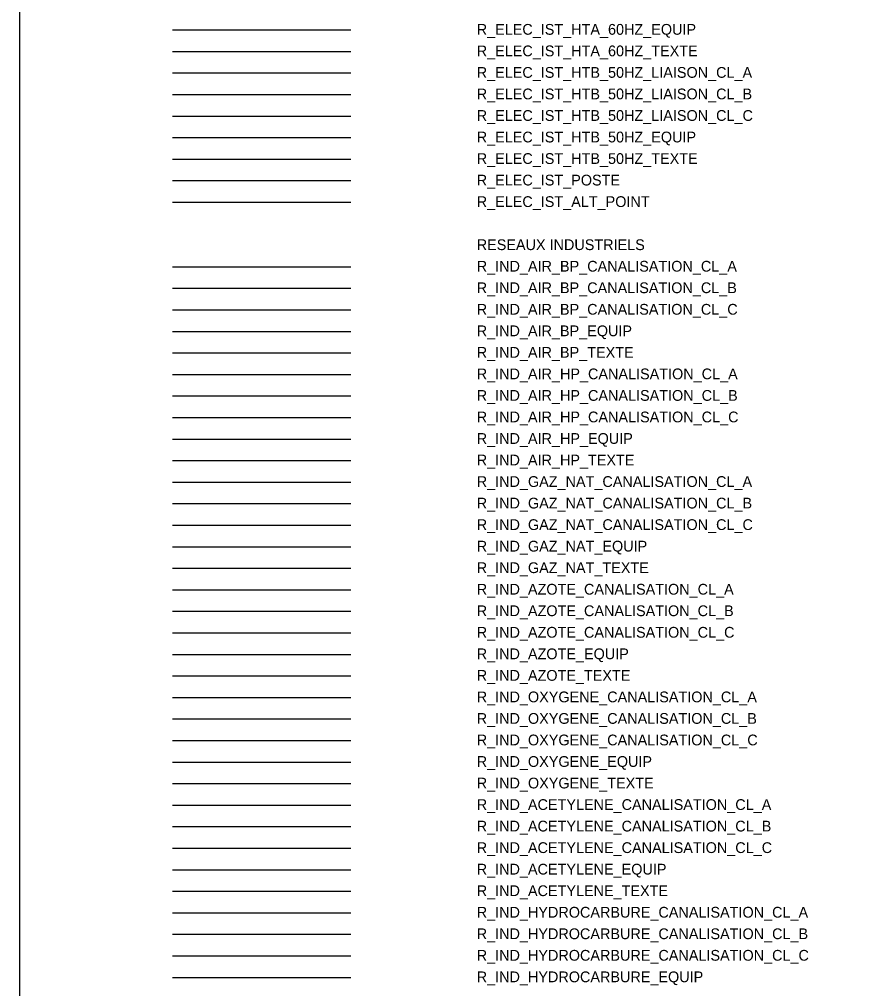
# Model space of a CAD drawing. Extents: x -60 to 214, y -380 to -21.
# Drawn here: x 33.07 to 72.77, y -155.95 to -110.94 of the extents above; entities that cross this region are included whole.
import ezdxf

# ---------------------------------------------------------------- set-up
doc = ezdxf.new("R2010")
doc.units = 0
for name, color, linetype in [('Default', 7, 'Continuous'), ('DH_TEXTE', 7, 'Continuous'), ('R_ELEC_IST_ALT_POINT', 7, 'Continuous'), ('R_ELEC_IST_HTA_60HZ_EQUIP', 7, 'Continuous'), ('R_ELEC_IST_HTA_60HZ_TEXTE', 7, 'Continuous'), ('R_ELEC_IST_HTB_50HZ_EQUIP', 7, 'Continuous'), ('R_ELEC_IST_HTB_50HZ_LIAISON_CL_A', 7, 'Continuous'), ('R_ELEC_IST_HTB_50HZ_LIAISON_CL_B', 7, 'Continuous'), ('R_ELEC_IST_HTB_50HZ_LIAISON_CL_C', 7, 'Continuous'), ('R_ELEC_IST_HTB_50HZ_TEXTE', 7, 'Continuous'), ('R_ELEC_IST_POSTE', 7, 'Continuous'), ('R_IND_ACETYLENE_CANALISATION_CL_A', 7, 'Continuous'), ('R_IND_ACETYLENE_CANALISATION_CL_B', 7, 'Continuous'), ('R_IND_ACETYLENE_CANALISATION_CL_C', 7, 'Continuous'), ('R_IND_ACETYLENE_EQUIP', 7, 'Continuous'), ('R_IND_ACETYLENE_TEXTE', 7, 'Continuous'), ('R_IND_AIR_BP_CANALISATION_CL_A', 7, 'Continuous'), ('R_IND_AIR_BP_CANALISATION_CL_B', 7, 'Continuous'), ('R_IND_AIR_BP_CANALISATION_CL_C', 7, 'Continuous'), ('R_IND_AIR_BP_EQUIP', 7, 'Continuous'), ('R_IND_AIR_BP_TEXTE', 7, 'Continuous'), ('R_IND_AIR_HP_CANALISATION_CL_A', 7, 'Continuous'), ('R_IND_AIR_HP_CANALISATION_CL_B', 7, 'Continuous'), ('R_IND_AIR_HP_CANALISATION_CL_C', 7, 'Continuous'), ('R_IND_AIR_HP_EQUIP', 7, 'Continuous'), ('R_IND_AIR_HP_TEXTE', 7, 'Continuous'), ('R_IND_AZOTE_CANALISATION_CL_A', 7, 'Continuous'), ('R_IND_AZOTE_CANALISATION_CL_B', 7, 'Continuous'), ('R_IND_AZOTE_CANALISATION_CL_C', 7, 'Continuous'), ('R_IND_AZOTE_EQUIP', 7, 'Continuous'), ('R_IND_AZOTE_TEXTE', 7, 'Continuous'), ('R_IND_GAZ_NAT_CANALISATION_CL_A', 7, 'Continuous'), ('R_IND_GAZ_NAT_CANALISATION_CL_B', 7, 'Continuous'), ('R_IND_GAZ_NAT_CANALISATION_CL_C', 7, 'Continuous'), ('R_IND_GAZ_NAT_EQUIP', 7, 'Continuous'), ('R_IND_GAZ_NAT_TEXTE', 7, 'Continuous'), ('R_IND_HYDROCARBURE_CANALISATION_CL_A', 7, 'Continuous'), ('R_IND_HYDROCARBURE_CANALISATION_CL_B', 7, 'Continuous'), ('R_IND_HYDROCARBURE_CANALISATION_CL_C', 7, 'Continuous'), ('R_IND_HYDROCARBURE_EQUIP', 7, 'Continuous'), ('R_IND_OXYGENE_CANALISATION_CL_A', 7, 'Continuous'), ('R_IND_OXYGENE_CANALISATION_CL_B', 7, 'Continuous'), ('R_IND_OXYGENE_CANALISATION_CL_C', 7, 'Continuous'), ('R_IND_OXYGENE_EQUIP', 7, 'Continuous'), ('R_IND_OXYGENE_TEXTE', 7, 'Continuous')]:
    doc.layers.add(name, color=color, linetype=linetype)

msp = doc.modelspace()

# ---------------------------------------------------------------- linework, layer by layer
at = {"layer": 'Default'}
msp.add_lwpolyline([(114.838, -25.727), (33.073, -25.727), (33.073, -380.216), (114.838, -380.216)], close=True, dxfattribs=at)
at = {"layer": 'R_ELEC_IST_ALT_POINT'}
msp.add_line((40.178, -119.429), (48.457, -119.429), dxfattribs=at)
at = {"layer": 'R_ELEC_IST_HTA_60HZ_EQUIP'}
msp.add_line((40.178, -111.429), (48.457, -111.429), dxfattribs=at)
at = {"layer": 'R_ELEC_IST_HTA_60HZ_TEXTE'}
msp.add_line((40.178, -112.429), (48.457, -112.429), dxfattribs=at)
at = {"layer": 'R_ELEC_IST_HTB_50HZ_EQUIP'}
msp.add_line((40.178, -116.429), (48.457, -116.429), dxfattribs=at)
at = {"layer": 'R_ELEC_IST_HTB_50HZ_LIAISON_CL_A'}
msp.add_line((40.178, -113.429), (48.457, -113.429), dxfattribs=at)
at = {"layer": 'R_ELEC_IST_HTB_50HZ_LIAISON_CL_B'}
msp.add_line((40.178, -114.429), (48.457, -114.429), dxfattribs=at)
at = {"layer": 'R_ELEC_IST_HTB_50HZ_LIAISON_CL_C'}
msp.add_line((40.178, -115.429), (48.457, -115.429), dxfattribs=at)
at = {"layer": 'R_ELEC_IST_HTB_50HZ_TEXTE'}
msp.add_line((40.178, -117.429), (48.457, -117.429), dxfattribs=at)
at = {"layer": 'R_ELEC_IST_POSTE'}
msp.add_line((40.178, -118.429), (48.457, -118.429), dxfattribs=at)
at = {"layer": 'R_IND_ACETYLENE_CANALISATION_CL_A'}
msp.add_line((40.178, -147.429), (48.457, -147.429), dxfattribs=at)
at = {"layer": 'R_IND_ACETYLENE_CANALISATION_CL_B'}
msp.add_line((40.178, -148.429), (48.457, -148.429), dxfattribs=at)
at = {"layer": 'R_IND_ACETYLENE_CANALISATION_CL_C'}
msp.add_line((40.178, -149.429), (48.457, -149.429), dxfattribs=at)
at = {"layer": 'R_IND_ACETYLENE_EQUIP'}
msp.add_line((40.178, -150.429), (48.457, -150.429), dxfattribs=at)
at = {"layer": 'R_IND_ACETYLENE_TEXTE'}
msp.add_line((40.178, -151.429), (48.457, -151.429), dxfattribs=at)
at = {"layer": 'R_IND_AIR_BP_CANALISATION_CL_A'}
msp.add_line((40.178, -122.429), (48.457, -122.429), dxfattribs=at)
at = {"layer": 'R_IND_AIR_BP_CANALISATION_CL_B'}
msp.add_line((40.178, -123.429), (48.457, -123.429), dxfattribs=at)
at = {"layer": 'R_IND_AIR_BP_CANALISATION_CL_C'}
msp.add_line((40.178, -124.429), (48.457, -124.429), dxfattribs=at)
at = {"layer": 'R_IND_AIR_BP_EQUIP'}
msp.add_line((40.178, -125.429), (48.457, -125.429), dxfattribs=at)
at = {"layer": 'R_IND_AIR_BP_TEXTE'}
msp.add_line((40.178, -126.429), (48.457, -126.429), dxfattribs=at)
at = {"layer": 'R_IND_AIR_HP_CANALISATION_CL_A'}
msp.add_line((40.178, -127.429), (48.457, -127.429), dxfattribs=at)
at = {"layer": 'R_IND_AIR_HP_CANALISATION_CL_B'}
msp.add_line((40.178, -128.429), (48.457, -128.429), dxfattribs=at)
at = {"layer": 'R_IND_AIR_HP_CANALISATION_CL_C'}
msp.add_line((40.178, -129.429), (48.457, -129.429), dxfattribs=at)
at = {"layer": 'R_IND_AIR_HP_EQUIP'}
msp.add_line((40.178, -130.429), (48.457, -130.429), dxfattribs=at)
at = {"layer": 'R_IND_AIR_HP_TEXTE'}
msp.add_line((40.178, -131.429), (48.457, -131.429), dxfattribs=at)
at = {"layer": 'R_IND_AZOTE_CANALISATION_CL_A'}
msp.add_line((40.178, -137.429), (48.457, -137.429), dxfattribs=at)
at = {"layer": 'R_IND_AZOTE_CANALISATION_CL_B'}
msp.add_line((40.178, -138.429), (48.457, -138.429), dxfattribs=at)
at = {"layer": 'R_IND_AZOTE_CANALISATION_CL_C'}
msp.add_line((40.178, -139.429), (48.457, -139.429), dxfattribs=at)
at = {"layer": 'R_IND_AZOTE_EQUIP'}
msp.add_line((40.178, -140.429), (48.457, -140.429), dxfattribs=at)
at = {"layer": 'R_IND_AZOTE_TEXTE'}
msp.add_line((40.178, -141.429), (48.457, -141.429), dxfattribs=at)
at = {"layer": 'R_IND_GAZ_NAT_CANALISATION_CL_A'}
msp.add_line((40.178, -132.429), (48.457, -132.429), dxfattribs=at)
at = {"layer": 'R_IND_GAZ_NAT_CANALISATION_CL_B'}
msp.add_line((40.178, -133.429), (48.457, -133.429), dxfattribs=at)
at = {"layer": 'R_IND_GAZ_NAT_CANALISATION_CL_C'}
msp.add_line((40.178, -134.429), (48.457, -134.429), dxfattribs=at)
at = {"layer": 'R_IND_GAZ_NAT_EQUIP'}
msp.add_line((40.178, -135.429), (48.457, -135.429), dxfattribs=at)
at = {"layer": 'R_IND_GAZ_NAT_TEXTE'}
msp.add_line((40.178, -136.429), (48.457, -136.429), dxfattribs=at)
at = {"layer": 'R_IND_HYDROCARBURE_CANALISATION_CL_A'}
msp.add_line((40.178, -152.429), (48.457, -152.429), dxfattribs=at)
at = {"layer": 'R_IND_HYDROCARBURE_CANALISATION_CL_B'}
msp.add_line((40.178, -153.429), (48.457, -153.429), dxfattribs=at)
at = {"layer": 'R_IND_HYDROCARBURE_CANALISATION_CL_C'}
msp.add_line((40.178, -154.429), (48.457, -154.429), dxfattribs=at)
at = {"layer": 'R_IND_HYDROCARBURE_EQUIP'}
msp.add_line((40.178, -155.429), (48.457, -155.429), dxfattribs=at)
at = {"layer": 'R_IND_OXYGENE_CANALISATION_CL_A'}
msp.add_line((40.178, -142.429), (48.457, -142.429), dxfattribs=at)
at = {"layer": 'R_IND_OXYGENE_CANALISATION_CL_B'}
msp.add_line((40.178, -143.429), (48.457, -143.429), dxfattribs=at)
at = {"layer": 'R_IND_OXYGENE_CANALISATION_CL_C'}
msp.add_line((40.178, -144.429), (48.457, -144.429), dxfattribs=at)
at = {"layer": 'R_IND_OXYGENE_EQUIP'}
msp.add_line((40.178, -145.429), (48.457, -145.429), dxfattribs=at)
at = {"layer": 'R_IND_OXYGENE_TEXTE'}
msp.add_line((40.178, -146.429), (48.457, -146.429), dxfattribs=at)

# ---------------------------------------------------------------- texts
at = {"layer": 'DH_TEXTE'}
msp.add_text('RESEAUX INDUSTRIELS ', height=0.5, dxfattribs=at).set_placement((54.301, -121.655))
at = {"layer": 'R_ELEC_IST_ALT_POINT'}
msp.add_text('R_ELEC_IST_ALT_POINT  ', height=0.5, dxfattribs=at).set_placement((54.301, -119.655))
at = {"layer": 'R_ELEC_IST_HTA_60HZ_EQUIP'}
msp.add_text('R_ELEC_IST_HTA_60HZ_EQUIP ', height=0.5, dxfattribs=at).set_placement((54.301, -111.655))
at = {"layer": 'R_ELEC_IST_HTA_60HZ_TEXTE'}
msp.add_text('R_ELEC_IST_HTA_60HZ_TEXTE ', height=0.5, dxfattribs=at).set_placement((54.301, -112.655))
at = {"layer": 'R_ELEC_IST_HTB_50HZ_EQUIP'}
msp.add_text('R_ELEC_IST_HTB_50HZ_EQUIP ', height=0.5, dxfattribs=at).set_placement((54.301, -116.655))
at = {"layer": 'R_ELEC_IST_HTB_50HZ_LIAISON_CL_A'}
msp.add_text('R_ELEC_IST_HTB_50HZ_LIAISON_CL_A ', height=0.5, dxfattribs=at).set_placement((54.301, -113.655))
at = {"layer": 'R_ELEC_IST_HTB_50HZ_LIAISON_CL_B'}
msp.add_text('R_ELEC_IST_HTB_50HZ_LIAISON_CL_B ', height=0.5, dxfattribs=at).set_placement((54.301, -114.655))
at = {"layer": 'R_ELEC_IST_HTB_50HZ_LIAISON_CL_C'}
msp.add_text('R_ELEC_IST_HTB_50HZ_LIAISON_CL_C ', height=0.5, dxfattribs=at).set_placement((54.301, -115.655))
at = {"layer": 'R_ELEC_IST_HTB_50HZ_TEXTE'}
msp.add_text('R_ELEC_IST_HTB_50HZ_TEXTE ', height=0.5, dxfattribs=at).set_placement((54.301, -117.655))
at = {"layer": 'R_ELEC_IST_POSTE'}
msp.add_text('R_ELEC_IST_POSTE ', height=0.5, dxfattribs=at).set_placement((54.301, -118.655))
at = {"layer": 'R_IND_ACETYLENE_CANALISATION_CL_A'}
msp.add_text('R_IND_ACETYLENE_CANALISATION_CL_A ', height=0.5, dxfattribs=at).set_placement((54.301, -147.655))
at = {"layer": 'R_IND_ACETYLENE_CANALISATION_CL_B'}
msp.add_text('R_IND_ACETYLENE_CANALISATION_CL_B ', height=0.5, dxfattribs=at).set_placement((54.301, -148.655))
at = {"layer": 'R_IND_ACETYLENE_CANALISATION_CL_C'}
msp.add_text('R_IND_ACETYLENE_CANALISATION_CL_C ', height=0.5, dxfattribs=at).set_placement((54.301, -149.655))
at = {"layer": 'R_IND_ACETYLENE_EQUIP'}
msp.add_text('R_IND_ACETYLENE_EQUIP ', height=0.5, dxfattribs=at).set_placement((54.301, -150.655))
at = {"layer": 'R_IND_ACETYLENE_TEXTE'}
msp.add_text('R_IND_ACETYLENE_TEXTE ', height=0.5, dxfattribs=at).set_placement((54.301, -151.655))
at = {"layer": 'R_IND_AIR_BP_CANALISATION_CL_A'}
msp.add_text('R_IND_AIR_BP_CANALISATION_CL_A ', height=0.5, dxfattribs=at).set_placement((54.301, -122.655))
at = {"layer": 'R_IND_AIR_BP_CANALISATION_CL_B'}
msp.add_text('R_IND_AIR_BP_CANALISATION_CL_B ', height=0.5, dxfattribs=at).set_placement((54.301, -123.655))
at = {"layer": 'R_IND_AIR_BP_CANALISATION_CL_C'}
msp.add_text('R_IND_AIR_BP_CANALISATION_CL_C ', height=0.5, dxfattribs=at).set_placement((54.301, -124.655))
at = {"layer": 'R_IND_AIR_BP_EQUIP'}
msp.add_text('R_IND_AIR_BP_EQUIP ', height=0.5, dxfattribs=at).set_placement((54.301, -125.655))
at = {"layer": 'R_IND_AIR_BP_TEXTE'}
msp.add_text('R_IND_AIR_BP_TEXTE ', height=0.5, dxfattribs=at).set_placement((54.301, -126.655))
at = {"layer": 'R_IND_AIR_HP_CANALISATION_CL_A'}
msp.add_text('R_IND_AIR_HP_CANALISATION_CL_A ', height=0.5, dxfattribs=at).set_placement((54.301, -127.655))
at = {"layer": 'R_IND_AIR_HP_CANALISATION_CL_B'}
msp.add_text('R_IND_AIR_HP_CANALISATION_CL_B ', height=0.5, dxfattribs=at).set_placement((54.301, -128.655))
at = {"layer": 'R_IND_AIR_HP_CANALISATION_CL_C'}
msp.add_text('R_IND_AIR_HP_CANALISATION_CL_C ', height=0.5, dxfattribs=at).set_placement((54.301, -129.655))
at = {"layer": 'R_IND_AIR_HP_EQUIP'}
msp.add_text('R_IND_AIR_HP_EQUIP ', height=0.5, dxfattribs=at).set_placement((54.301, -130.655))
at = {"layer": 'R_IND_AIR_HP_TEXTE'}
msp.add_text('R_IND_AIR_HP_TEXTE ', height=0.5, dxfattribs=at).set_placement((54.301, -131.655))
at = {"layer": 'R_IND_AZOTE_CANALISATION_CL_A'}
msp.add_text('R_IND_AZOTE_CANALISATION_CL_A ', height=0.5, dxfattribs=at).set_placement((54.301, -137.655))
at = {"layer": 'R_IND_AZOTE_CANALISATION_CL_B'}
msp.add_text('R_IND_AZOTE_CANALISATION_CL_B ', height=0.5, dxfattribs=at).set_placement((54.301, -138.655))
at = {"layer": 'R_IND_AZOTE_CANALISATION_CL_C'}
msp.add_text('R_IND_AZOTE_CANALISATION_CL_C ', height=0.5, dxfattribs=at).set_placement((54.301, -139.655))
at = {"layer": 'R_IND_AZOTE_EQUIP'}
msp.add_text('R_IND_AZOTE_EQUIP ', height=0.5, dxfattribs=at).set_placement((54.301, -140.655))
at = {"layer": 'R_IND_AZOTE_TEXTE'}
msp.add_text('R_IND_AZOTE_TEXTE ', height=0.5, dxfattribs=at).set_placement((54.301, -141.655))
at = {"layer": 'R_IND_GAZ_NAT_CANALISATION_CL_A'}
msp.add_text('R_IND_GAZ_NAT_CANALISATION_CL_A ', height=0.5, dxfattribs=at).set_placement((54.301, -132.655))
at = {"layer": 'R_IND_GAZ_NAT_CANALISATION_CL_B'}
msp.add_text('R_IND_GAZ_NAT_CANALISATION_CL_B ', height=0.5, dxfattribs=at).set_placement((54.301, -133.655))
at = {"layer": 'R_IND_GAZ_NAT_CANALISATION_CL_C'}
msp.add_text('R_IND_GAZ_NAT_CANALISATION_CL_C ', height=0.5, dxfattribs=at).set_placement((54.301, -134.655))
at = {"layer": 'R_IND_GAZ_NAT_EQUIP'}
msp.add_text('R_IND_GAZ_NAT_EQUIP ', height=0.5, dxfattribs=at).set_placement((54.301, -135.655))
at = {"layer": 'R_IND_GAZ_NAT_TEXTE'}
msp.add_text('R_IND_GAZ_NAT_TEXTE ', height=0.5, dxfattribs=at).set_placement((54.301, -136.655))
at = {"layer": 'R_IND_HYDROCARBURE_CANALISATION_CL_A'}
msp.add_text('R_IND_HYDROCARBURE_CANALISATION_CL_A ', height=0.5, dxfattribs=at).set_placement((54.301, -152.655))
at = {"layer": 'R_IND_HYDROCARBURE_CANALISATION_CL_B'}
msp.add_text('R_IND_HYDROCARBURE_CANALISATION_CL_B ', height=0.5, dxfattribs=at).set_placement((54.301, -153.655))
at = {"layer": 'R_IND_HYDROCARBURE_CANALISATION_CL_C'}
msp.add_text('R_IND_HYDROCARBURE_CANALISATION_CL_C ', height=0.5, dxfattribs=at).set_placement((54.301, -154.655))
at = {"layer": 'R_IND_HYDROCARBURE_EQUIP'}
msp.add_text('R_IND_HYDROCARBURE_EQUIP ', height=0.5, dxfattribs=at).set_placement((54.301, -155.655))
at = {"layer": 'R_IND_OXYGENE_CANALISATION_CL_A'}
msp.add_text('R_IND_OXYGENE_CANALISATION_CL_A ', height=0.5, dxfattribs=at).set_placement((54.301, -142.655))
at = {"layer": 'R_IND_OXYGENE_CANALISATION_CL_B'}
msp.add_text('R_IND_OXYGENE_CANALISATION_CL_B ', height=0.5, dxfattribs=at).set_placement((54.301, -143.655))
at = {"layer": 'R_IND_OXYGENE_CANALISATION_CL_C'}
msp.add_text('R_IND_OXYGENE_CANALISATION_CL_C ', height=0.5, dxfattribs=at).set_placement((54.301, -144.655))
at = {"layer": 'R_IND_OXYGENE_EQUIP'}
msp.add_text('R_IND_OXYGENE_EQUIP ', height=0.5, dxfattribs=at).set_placement((54.301, -145.655))
at = {"layer": 'R_IND_OXYGENE_TEXTE'}
msp.add_text('R_IND_OXYGENE_TEXTE ', height=0.5, dxfattribs=at).set_placement((54.301, -146.655))

doc.saveas('drawing.dxf')
